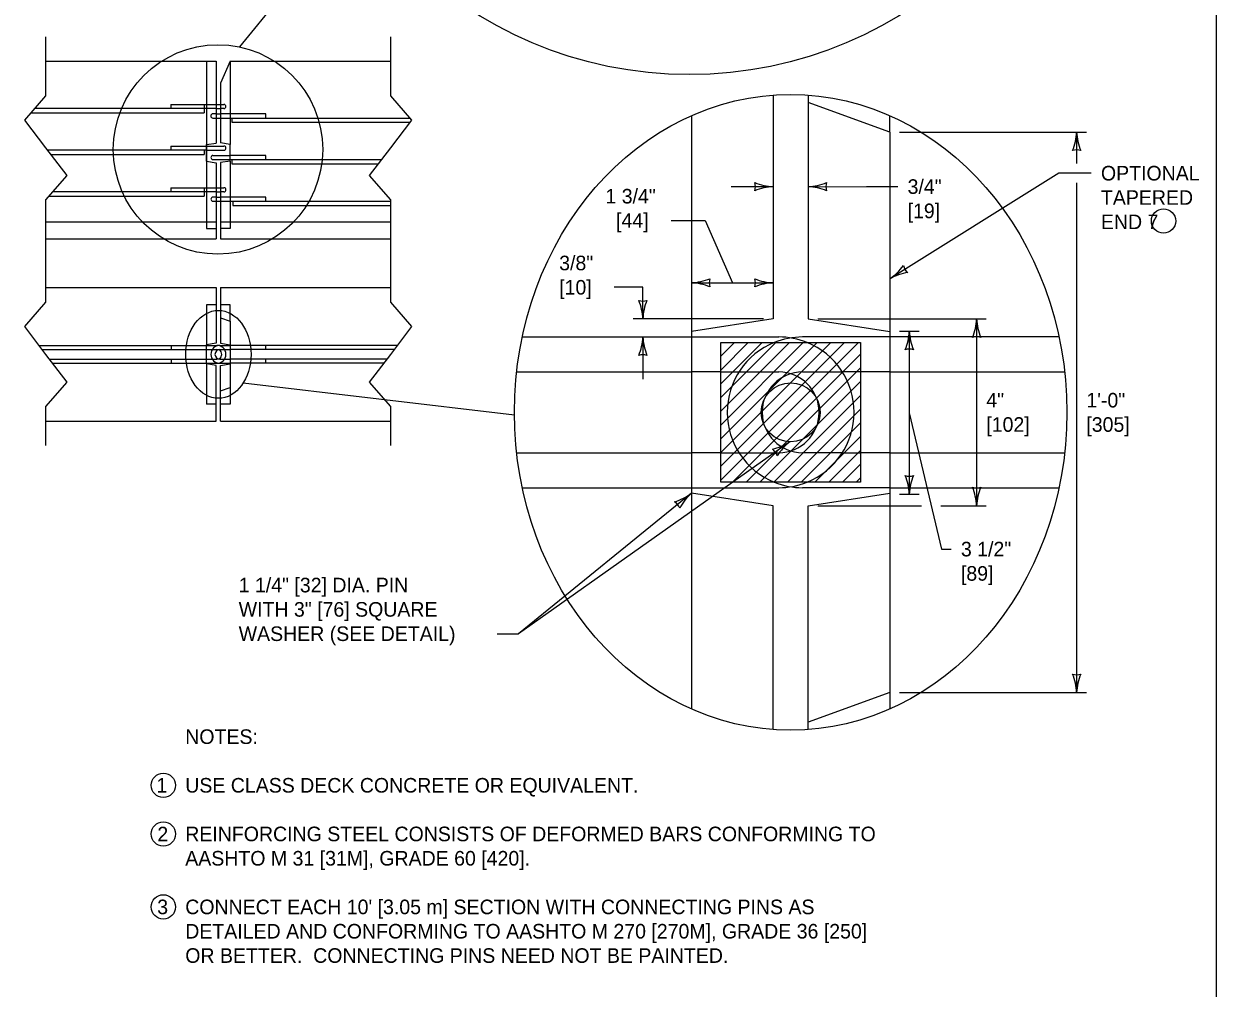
# Model space of a CAD drawing. Extents: x 49991.4 to 50021, y 49987.6 to 50011.4.
# Drawn here: x 50011.847 to 50016.75, y 49991.688 to 49995.652 of the extents above; entities that cross this region are included whole.
import ezdxf

# ---------------------------------------------------------------- set-up
doc = ezdxf.new("R2010")
doc.units = 0
for name, color, linetype in [('Level 1', 7, 'Continuous'), ('Level 2', 7, 'Continuous'), ('Level 3', 7, 'Continuous'), ('Level 4', 7, 'Continuous'), ('Level 6', 7, 'Continuous')]:
    doc.layers.add(name, color=color, linetype=linetype)

msp = doc.modelspace()

# ---------------------------------------------------------------- linework, layer by layer
at = {"layer": 'Level 1'}
for p, q in [((50011.938, 49995.4997), (50012.6382, 49995.4997)), ((50012.6382, 49995.4997), (50012.6382, 49995.1617)), ((50012.6954, 49995.4997), (50012.6554, 49995.4086)), ((50012.6954, 49995.4997), (50013.3556, 49995.4997)), ((50012.6554, 49995.4086), (50012.6554, 49995.163)), ((50014.9286, 49995.3595), (50014.9286, 49994.4393)), ((50015.072, 49995.3595), (50015.072, 49994.4393)), ((50012.6382, 49995.3211), (50012.6554, 49995.3211)), ((50015.4082, 49995.2072), (50015.072, 49995.3287)), ((50012.6382, 49995.3041), (50012.6554, 49995.3041)), ((50012.6382, 49995.2825), (50012.6554, 49995.2825)), ((50012.6382, 49995.2652), (50012.6554, 49995.2652)), ((50012.5984, 49995.157), (50012.6382, 49995.1617)), ((50012.6954, 49995.157), (50012.6554, 49995.163)), ((50015.4082, 49995.2072), (50015.4082, 49992.9029)), ((50012.5984, 49995.0885), (50012.5984, 49995.157)), ((50012.5984, 49995.1501), (50012.6695, 49995.1501)), ((50012.5984, 49995.133), (50012.6695, 49995.133)), ((50012.6245, 49995.1114), (50012.6956, 49995.1114)), ((50012.6954, 49995.0885), (50012.6954, 49995.157)), ((50012.5984, 49995.0885), (50012.6382, 49995.0811)), ((50012.6245, 49995.0943), (50012.6956, 49995.0943)), ((50012.6384, 49995.0811), (50012.6384, 49994.7681)), ((50012.6954, 49995.0885), (50012.6554, 49995.0825)), ((50012.6554, 49995.0825), (50012.6554, 49994.7681)), ((50012.6384, 49994.9789), (50012.6554, 49994.9789)), ((50012.6384, 49994.9617), (50012.6554, 49994.9617)), ((50012.6384, 49994.9401), (50012.6554, 49994.9401)), ((50012.6384, 49994.923), (50012.6554, 49994.923)), ((50011.938, 49994.7681), (50012.6384, 49994.7681)), ((50012.6554, 49994.7681), (50013.3556, 49994.7681)), ((50011.938, 49994.5681), (50012.6382, 49994.5681)), ((50012.6382, 49994.5681), (50012.6382, 49994.3394)), ((50012.6554, 49994.5681), (50013.3556, 49994.5681)), ((50012.6554, 49994.5681), (50012.6554, 49994.3394)), ((50012.6554, 49994.4437), (50012.6957, 49994.4294)), ((50012.6957, 49994.4294), (50012.6954, 49994.1578)), ((50014.9286, 49994.4393), (50014.5924, 49994.3877)), ((50015.072, 49994.4393), (50015.4082, 49994.3877)), ((50014.5924, 49994.3877), (50014.5924, 49993.7225)), ((50012.6382, 49994.3394), (50012.5984, 49994.3332)), ((50012.5984, 49994.254), (50012.5984, 49994.3332)), ((50012.5984, 49994.3306), (50012.6411, 49994.3306)), ((50012.6528, 49994.3305), (50012.6956, 49994.3305)), ((50012.6554, 49994.3394), (50012.6956, 49994.3332)), ((50014.5924, 49994.365), (50014.9512, 49994.3651)), ((50014.713, 49994.3423), (50015.2876, 49994.3423)), ((50014.713, 49993.7679), (50014.713, 49994.3423)), ((50014.713, 49994.3423), (50014.713, 49994.3423)), ((50014.713, 49994.2857), (50014.7696, 49994.3423)), ((50014.713, 49994.2292), (50014.8261, 49994.3423)), ((50014.713, 49994.1726), (50014.8827, 49994.3423)), ((50014.713, 49994.116), (50014.9393, 49994.3423)), ((50014.713, 49994.0595), (50014.9958, 49994.3423)), ((50014.713, 49994.0029), (50015.0524, 49994.3423)), ((50014.713, 49993.9463), (50015.109, 49994.3423)), ((50014.713, 49993.8898), (50015.1655, 49994.3423)), ((50014.713, 49993.8332), (50015.2221, 49994.3423)), ((50014.713, 49993.7766), (50015.2787, 49994.3423)), ((50015.4082, 49994.3651), (50015.0495, 49994.3651)), ((50015.2876, 49994.3423), (50015.2876, 49993.7679)), ((50012.5984, 49994.3134), (50012.6411, 49994.3134)), ((50012.6528, 49994.3134), (50012.6956, 49994.3134)), ((50014.7609, 49993.7679), (50015.2876, 49994.2946)), ((50012.5984, 49994.2738), (50012.6411, 49994.2738)), ((50012.5984, 49994.2567), (50012.6411, 49994.2567)), ((50012.6382, 49994.2479), (50012.5984, 49994.254)), ((50012.6382, 49994.0191), (50012.6382, 49994.2479)), ((50012.6528, 49994.2738), (50012.6955, 49994.2738)), ((50012.6528, 49994.2567), (50012.6955, 49994.2567)), ((50012.6554, 49994.2479), (50012.6955, 49994.254)), ((50012.6554, 49994.0191), (50012.6554, 49994.2479)), ((50014.8174, 49993.7679), (50015.2876, 49994.2381)), ((50014.713, 49994.2214), (50014.5924, 49994.2214)), ((50014.874, 49993.7679), (50015.2876, 49994.1815)), ((50015.4082, 49994.2214), (50015.2876, 49994.2214)), ((50012.6554, 49994.1435), (50012.6954, 49994.1578)), ((50014.9306, 49993.7679), (50015.2876, 49994.1249)), ((50014.9871, 49993.7679), (50015.2876, 49994.0684)), ((50011.938, 49994.0191), (50012.6382, 49994.0191)), ((50012.6554, 49994.0191), (50013.3556, 49994.0191)), ((50015.0437, 49993.7679), (50015.2876, 49994.0118)), ((50015.1003, 49993.7679), (50015.2877, 49993.9553)), ((50014.713, 49993.8886), (50014.5924, 49993.8886)), ((50015.1568, 49993.7679), (50015.2876, 49993.8987)), ((50015.4082, 49993.8886), (50015.2876, 49993.8886)), ((50015.2134, 49993.7679), (50015.2876, 49993.8421)), ((50014.5924, 49993.7451), (50014.9512, 49993.7452)), ((50015.2876, 49993.7679), (50014.713, 49993.7679)), ((50015.4082, 49993.7452), (50015.0494, 49993.7452)), ((50015.27, 49993.7679), (50015.2876, 49993.7855)), ((50014.9286, 49993.6712), (50014.5924, 49993.7225)), ((50015.072, 49993.6712), (50015.4082, 49993.7225)), ((50014.9286, 49992.7507), (50014.9286, 49993.6712)), ((50015.072, 49992.7507), (50015.072, 49993.6712)), ((50015.4082, 49992.9029), (50015.072, 49992.7814))]:
    msp.add_line(p, q, dxfattribs=at)
msp.add_lwpolyline([(49999.3835, 49998.9992), (50016.7501, 49998.9992), (50016.7501, 49987.7988), (49999.3835, 49987.7988)], close=True, dxfattribs=at)
msp.add_circle((50015.0004, 49994.0551), 0.121, dxfattribs=at)
msp.add_circle((50015.0004, 49994.0551), 0.121, dxfattribs=at)
for centre, radius, start, end in [((50012.6245, 49995.1029), 0.00855, 90, 270), ((50012.6695, 49995.1416), 0.00855, 270, 90), ((50012.6528, 49994.2936), 0.0369, 90, 270), ((50012.6411, 49994.2937), 0.0369, 270, 90), ((50015.0498, 49994.0538), 0.3112, 90.0536, 112.055), ((50014.9512, 49994.0551), 0.31, 67.9034, 90), ((50012.6528, 49994.2936), 0.0198, 90, 270), ((50012.6411, 49994.2936), 0.0198, 269.9309, 90.0691), ((50015.0485, 49994.0503), 0.3051, 247.7572, 270.175), ((50014.9512, 49994.0551), 0.31, 270, 292.0834)]:
    msp.add_arc(centre, radius, start, end, dxfattribs=at)
at = {"layer": 'Level 2'}
for centre in [(50016.5337, 49994.8418), (50012.4207, 49992.5217), (50012.4207, 49992.3217), (50012.4207, 49992.0217)]:
    msp.add_circle(centre, 0.05, dxfattribs=at)
at = {"layer": 'Level 3'}
for p, q in [((50013.221, 49996.1563), (50012.7333, 49995.5574)), ((50015.4482, 49995.2072), (50016.2163, 49995.2072)), ((50016.1763, 49995.2072), (50016.1763, 49995.0784)), ((50016.1031, 49995.0384), (50015.4082, 49994.6041)), ((50016.2363, 49995.0384), (50016.1031, 49995.0384)), ((50014.9286, 49994.983), (50014.7552, 49994.983)), ((50016.1763, 49994.9984), (50016.1763, 49992.9029)), ((50014.5924, 49994.5878), (50014.9286, 49994.5878)), ((50014.3926, 49994.5692), (50014.275, 49994.5692)), ((50014.3926, 49994.4392), (50014.3926, 49994.5692)), ((50014.8886, 49994.4393), (50014.3526, 49994.4392)), ((50015.112, 49994.4393), (50015.8049, 49994.4392)), ((50015.7649, 49994.4392), (50015.7649, 49993.6711)), ((50015.4482, 49994.3884), (50015.5282, 49994.3884)), ((50015.4882, 49994.3884), (50015.4882, 49993.7192)), ((50014.3926, 49994.365), (50014.3926, 49994.1916)), ((50013.8643, 49994.0439), (50012.7486, 49994.1753)), ((50014.9971, 49993.9342), (50013.881, 49993.145)), ((50014.5924, 49993.7225), (50013.881, 49993.145)), ((50015.4482, 49993.7192), (50015.5282, 49993.7192)), ((50015.112, 49993.6711), (50015.5384, 49993.6711)), ((50015.6184, 49993.6711), (50015.8049, 49993.6711)), ((50013.7928, 49993.145), (50013.881, 49993.145)), ((50015.4482, 49992.9029), (50016.2163, 49992.9029))]:
    msp.add_line(p, q, dxfattribs=at)
for points in [[(50015.072, 49994.983), (50015.3123, 49994.9834), (50015.4412, 49994.9834)], [(50014.509, 49994.8439), (50014.6482, 49994.8439), (50014.7606, 49994.5878)], [(50015.4882, 49994.0538), (50015.6204, 49993.4929), (50015.6605, 49993.4929)]]:
    msp.add_lwpolyline(points, dxfattribs=at)
for centre, radius in [((50014.5834, 49997.1025), 1.6587), ((50012.6453, 49995.136), 0.4305)]:
    msp.add_circle(centre, radius, dxfattribs=at)
for centre, radius, start, end in [((50015.9542, 49995.2164), 0.2223, 337.456, 357.6395), ((50016.4091, 49995.2187), 0.233, 182.8273, 202.0772), ((50016.1763, 49995.079), 0.0548, 72.1388, 107.8612), ((50014.9378, 49995.2051), 0.2223, 247.456, 267.6395), ((50014.8004, 49994.983), 0.0548, 342.1388, 17.8612), ((50014.9401, 49994.7503), 0.233, 92.8273, 112.0772), ((50015.0601, 49995.2157), 0.233, 272.9201, 292.17), ((50015.0632, 49994.7609), 0.2223, 67.5488, 87.7323), ((50015.2002, 49994.9832), 0.0548, 162.2316, 197.954), ((50015.2751, 49994.7953), 0.233, 304.8333, 324.0832), ((50015.5182, 49994.4109), 0.2223, 99.462, 119.6455), ((50015.5169, 49994.672), 0.0548, 194.1448, 229.8672), ((50014.5809, 49994.8205), 0.233, 272.8273, 292.0772), ((50014.5832, 49994.3657), 0.2223, 67.456, 87.6395), ((50014.7206, 49994.5878), 0.0548, 162.1388, 197.8612), ((50014.9378, 49994.8099), 0.2223, 247.456, 267.6395), ((50014.8004, 49994.5878), 0.0548, 342.1388, 17.8612), ((50014.9401, 49994.3551), 0.233, 92.8273, 112.0772), ((50014.3926, 49994.5675), 0.0548, 252.1388, 287.8612), ((50014.1599, 49994.4278), 0.233, 2.8273, 22.0772), ((50014.6147, 49994.4301), 0.2223, 157.456, 177.6395), ((50015.5428, 49994.4484), 0.2223, 337.456, 357.6395), ((50015.9977, 49994.4507), 0.233, 182.8273, 202.0772), ((50015.2661, 49994.3976), 0.2223, 337.456, 357.6395), ((50015.7209, 49994.3999), 0.233, 182.8273, 202.0772), ((50014.1705, 49994.3742), 0.2223, 337.456, 357.6395), ((50014.6253, 49994.3765), 0.233, 182.8273, 202.0772), ((50015.7649, 49994.311), 0.0548, 72.1388, 107.8612), ((50014.3926, 49994.2368), 0.0548, 72.1388, 107.8612), ((50015.4882, 49994.2602), 0.0548, 72.1388, 107.8612), ((50014.8763, 49994.1209), 0.2223, 282.7214, 302.9049), ((50015.1408, 49993.7508), 0.233, 128.0927, 147.3425), ((50014.8924, 49993.8602), 0.0548, 17.4042, 53.1265), ((50015.4882, 49993.8474), 0.0548, 252.1388, 287.8612), ((50015.2555, 49993.7077), 0.233, 2.8273, 22.0772), ((50015.7103, 49993.71), 0.2223, 157.456, 177.6395), ((50015.7649, 49993.7994), 0.0548, 252.1388, 287.8612), ((50015.5322, 49993.6596), 0.233, 2.8273, 22.0772), ((50015.9871, 49993.662), 0.2223, 157.456, 177.6395), ((50014.4595, 49993.9007), 0.2223, 286.5258, 306.7093), ((50014.748, 49993.5491), 0.233, 131.8971, 151.1469), ((50014.4929, 49993.6417), 0.0548, 21.2086, 56.931), ((50016.1763, 49993.0312), 0.0548, 252.1388, 287.8612), ((50015.9436, 49992.8915), 0.233, 2.8273, 22.0772), ((50016.3985, 49992.8938), 0.2223, 157.456, 177.6395)]:
    msp.add_arc(centre, radius, start, end, dxfattribs=at)
for centre, major_axis, ratio in [((50015.0003, 49994.0551), (0, -1.307), 0.869184), ((50012.647, 49994.2936), (0, -0.1808), 0.743274)]:
    msp.add_ellipse(centre, major_axis=major_axis, ratio=ratio, dxfattribs=at)
at = {"layer": 'Level 4'}
for p, q in [((50012.5984, 49995.4997), (50012.5984, 49994.8109)), ((50012.6954, 49995.4999), (50012.6954, 49995.157)), ((50012.451, 49995.3211), (50012.6382, 49995.3211)), ((50012.451, 49995.3211), (50012.451, 49995.3041)), ((50012.5878, 49995.3211), (50012.5878, 49995.3041)), ((50012.6554, 49995.3211), (50012.6695, 49995.3211)), ((50011.8769, 49995.2868), (50012.5878, 49995.2868)), ((50012.6382, 49995.3041), (50011.8921, 49995.3041)), ((50012.5878, 49995.3041), (50012.5878, 49995.2868)), ((50012.6382, 49995.2825), (50012.6245, 49995.2825)), ((50012.6245, 49995.2652), (50012.6382, 49995.2652)), ((50012.6695, 49995.3041), (50012.6554, 49995.3041)), ((50012.8426, 49995.2825), (50012.6554, 49995.2825)), ((50012.6554, 49995.2652), (50013.4356, 49995.2652)), ((50012.7024, 49995.2652), (50012.7024, 49995.2482)), ((50012.8426, 49995.2652), (50012.8426, 49995.2825)), ((50014.5924, 49995.2749), (50014.5924, 49994.3877)), ((50015.4082, 49995.2072), (50015.4082, 49995.275)), ((50012.7024, 49995.2482), (50013.4361, 49995.2482)), ((50012.5984, 49995.133), (50011.9455, 49995.133)), ((50011.9585, 49995.1159), (50012.5878, 49995.1159)), ((50012.451, 49995.1501), (50012.5984, 49995.1501)), ((50012.451, 49995.1501), (50012.451, 49995.133)), ((50012.5878, 49995.133), (50012.5878, 49995.1159)), ((50012.8426, 49995.1114), (50012.6956, 49995.1114)), ((50012.8426, 49995.0943), (50012.8426, 49995.1114)), ((50012.6954, 49995.0885), (50012.6954, 49994.8109)), ((50012.6956, 49995.0943), (50013.3186, 49995.0943)), ((50012.7024, 49995.0943), (50012.7024, 49995.0773)), ((50012.7024, 49995.0773), (50013.3056, 49995.0773)), ((50012.451, 49994.9789), (50012.6384, 49994.9789)), ((50012.451, 49994.9789), (50012.451, 49994.9617)), ((50012.5878, 49994.9789), (50012.5878, 49994.9617)), ((50012.6554, 49994.9789), (50012.6695, 49994.9789)), ((50011.9517, 49994.9446), (50012.5878, 49994.9446)), ((50012.6384, 49994.9617), (50011.9666, 49994.9617)), ((50012.5878, 49994.9617), (50012.5878, 49994.9446)), ((50012.6384, 49994.9401), (50012.6245, 49994.9401)), ((50012.6245, 49994.923), (50012.6384, 49994.923)), ((50012.6695, 49994.9617), (50012.6554, 49994.9617)), ((50012.8426, 49994.9401), (50012.6554, 49994.9401)), ((50012.6554, 49994.923), (50013.3556, 49994.923)), ((50012.7058, 49994.923), (50012.7058, 49994.9059)), ((50012.8426, 49994.923), (50012.8426, 49994.9401)), ((50012.7058, 49994.9059), (50013.3556, 49994.9059)), ((50012.6384, 49994.8365), (50011.938, 49994.8365)), ((50013.3556, 49994.8365), (50012.6554, 49994.8365)), ((50012.5984, 49994.8109), (50012.6384, 49994.8109)), ((50012.6954, 49994.8109), (50012.6554, 49994.8109)), ((50012.5984, 49994.4973), (50012.5984, 49994.3332)), ((50012.6382, 49994.4973), (50012.5984, 49994.4973)), ((50012.6957, 49994.4973), (50012.6554, 49994.4973)), ((50012.6957, 49994.4294), (50012.6957, 49994.4973)), ((50011.9097, 49994.3306), (50012.5984, 49994.3306)), ((50012.4538, 49994.3134), (50012.4538, 49994.3306)), ((50013.3838, 49994.3305), (50012.6956, 49994.3305)), ((50012.8426, 49994.3134), (50012.8426, 49994.3305)), ((50013.8967, 49994.365), (50014.5924, 49994.365)), ((50016.1039, 49994.3651), (50015.4082, 49994.3651)), ((50011.9229, 49994.3134), (50012.5984, 49994.3134)), ((50013.3707, 49994.3134), (50012.6956, 49994.3134)), ((50011.9531, 49994.2738), (50012.5984, 49994.2738)), ((50011.9662, 49994.2567), (50012.5984, 49994.2567)), ((50012.4538, 49994.2567), (50012.4538, 49994.2738)), ((50012.5984, 49994.254), (50012.5984, 49994.0885)), ((50013.3405, 49994.2738), (50012.6955, 49994.2738)), ((50013.3274, 49994.2567), (50012.6955, 49994.2567)), ((50012.8426, 49994.2567), (50012.8426, 49994.2738)), ((50013.8735, 49994.2214), (50014.5924, 49994.2214)), ((50014.713, 49994.2214), (50014.7881, 49994.2214)), ((50014.788, 49994.2215), (50014.9514, 49994.2215)), ((50015.0494, 49994.2215), (50015.2128, 49994.2215)), ((50015.2876, 49994.2214), (50015.2129, 49994.2214)), ((50015.4082, 49994.2214), (50016.1271, 49994.2214)), ((50012.6954, 49994.1578), (50012.6954, 49994.0885)), ((50012.6382, 49994.0885), (50012.5984, 49994.0885)), ((50012.6954, 49994.0885), (50012.6554, 49994.0885)), ((50013.8735, 49993.8886), (50014.5924, 49993.8886)), ((50014.713, 49993.8886), (50014.7881, 49993.8886)), ((50014.788, 49993.8887), (50014.9514, 49993.8887)), ((50015.2128, 49993.8887), (50015.0494, 49993.8887)), ((50015.2129, 49993.8886), (50015.2876, 49993.8886)), ((50015.4082, 49993.8886), (50016.1271, 49993.8886)), ((50013.8967, 49993.7451), (50014.5924, 49993.7451)), ((50015.4082, 49993.7452), (50016.104, 49993.7452)), ((50014.5924, 49993.7225), (50014.5924, 49992.8352)), ((50015.4082, 49992.9029), (50015.4082, 49992.8352))]:
    msp.add_line(p, q, dxfattribs=at)
for centre, radius, start, end in [((50012.6695, 49995.3126), 0.0085, 270, 90), ((50012.6245, 49995.2739), 0.00866, 90, 270), ((50012.6695, 49994.9703), 0.0086, 270, 90), ((50012.6245, 49994.9316), 0.00855, 90, 270), ((50015.0495, 49994.0551), 0.31, 112.0966, 247.9166), ((50014.9512, 49994.0551), 0.31, 292.0834, 67.9034), ((50015.0495, 49994.0551), 0.1663, 90, 270), ((50014.9512, 49994.0551), 0.1663, 270, 90)]:
    msp.add_arc(centre, radius, start, end, dxfattribs=at)
at = {"layer": 'Level 6'}
for p, q in [((50011.938, 49995.3567), (50011.938, 49995.5997)), ((50013.3556, 49995.3567), (50013.3556, 49995.5997)), ((50011.8508, 49995.2569), (50011.938, 49995.3567)), ((50013.4428, 49995.2569), (50013.3556, 49995.3567)), ((50011.938, 49995.1428), (50011.8508, 49995.2569)), ((50013.3556, 49995.1428), (50013.4428, 49995.2569)), ((50012.0252, 49995.0287), (50011.938, 49995.1428)), ((50013.2684, 49995.0287), (50013.3556, 49995.1428)), ((50011.938, 49994.929), (50012.0252, 49995.0287)), ((50013.3556, 49994.929), (50013.2684, 49995.0287)), ((50011.938, 49994.6681), (50011.938, 49994.929)), ((50013.3556, 49994.6681), (50013.3556, 49994.929)), ((50011.938, 49994.5075), (50011.938, 49994.6681)), ((50013.3556, 49994.5075), (50013.3556, 49994.6681)), ((50011.8508, 49994.4078), (50011.938, 49994.5075)), ((50013.4428, 49994.4078), (50013.3556, 49994.5075)), ((50011.938, 49994.2936), (50011.8508, 49994.4078)), ((50013.3556, 49994.2936), (50013.4428, 49994.4078)), ((50012.0252, 49994.1795), (50011.938, 49994.2936)), ((50013.2684, 49994.1795), (50013.3556, 49994.2936)), ((50011.938, 49994.0798), (50012.0252, 49994.1795)), ((50013.3556, 49994.0798), (50013.2684, 49994.1795)), ((50011.938, 49993.9191), (50011.938, 49994.0798)), ((50013.3556, 49993.9191), (50013.3556, 49994.0798))]:
    msp.add_line(p, q, dxfattribs=at)

# ---------------------------------------------------------------- texts
at = {"layer": 'Level 2'}
for s, p in [('OPTIONAL', (50016.2763, 49995.0084)), ('3/4"', (50015.4812, 49994.9534)), ('1 3/4"', (50014.2387, 49994.9139)), ('TAPERED ', (50016.2763, 49994.9084)), ('[19]', (50015.4812, 49994.8534)), ('[44]', (50014.2824, 49994.8139)), ('END 7', (50016.2763, 49994.8084)), ('3/8"', (50014.0484, 49994.6392)), ('[10]', (50014.0484, 49994.5392)), ('4"', (50015.8049, 49994.0752)), ('1\'-0"', (50016.2163, 49994.0751)), ('[102]', (50015.8049, 49993.9752)), ('[305]', (50016.2163, 49993.9751)), ('3 1/2"', (50015.7005, 49993.4629)), ('[89]', (50015.7005, 49993.3629)), ('1 1/4" [32] DIA. PIN', (50012.7304, 49993.315)), ('WITH 3" [76] SQUARE', (50012.7304, 49993.215)), ('WASHER (SEE DETAIL)', (50012.7304, 49993.115)), ('NOTES:', (50012.5107, 49992.6917)), ('1', (50012.3921, 49992.4917)), ('USE CLASS DECK CONCRETE OR EQUIVALENT.', (50012.5107, 49992.4917)), ('2', (50012.3959, 49992.2911)), ('REINFORCING STEEL CONSISTS OF DEFORMED BARS CONFORMING TO', (50012.5107, 49992.2917)), ('AASHTO M 31 [31M], GRADE 60 [420].  ', (50012.5107, 49992.1917)), ('3', (50012.3955, 49991.9917)), ("CONNECT EACH 10' [3.05 m] SECTION WITH CONNECTING PINS AS ", (50012.5107, 49991.9917)), ('DETAILED AND CONFORMING TO AASHTO M 270 [270M], GRADE 36 [250]', (50012.5107, 49991.8917)), ('OR BETTER.  CONNECTING PINS NEED NOT BE PAINTED.', (50012.5107, 49991.7917))]:
    msp.add_text(s, height=0.06, dxfattribs=at).set_placement(p)

doc.saveas('drawing.dxf')
